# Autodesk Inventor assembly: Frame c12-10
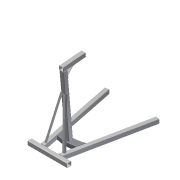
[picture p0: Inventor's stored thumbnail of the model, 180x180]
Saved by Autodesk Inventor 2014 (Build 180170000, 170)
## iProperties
Created: 2011-01
Part Number: Frame c12-10
Document SubType Name: Assembly
Designer: Thom Tremblay
_FrameDoc: Frame Assembly
_Version: 15.0.0
Author: Thom Tremblay
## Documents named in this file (20)
- C:\Inventor 2014 Essentials\Assemblies\Chapter 12\Frame\Frame c12-10.iam
- C:\Inventor 2014 Essentials\Assemblies\Chapter 12\Frame\Skeleton-c12-10.ipt
- C:\Inventor 2014 Essentials\Assemblies\Chapter 12\Frame\ANSI L 1.5 x 1.5 x 3_16 00000005.ipt
- ANSI L 1.5 x 1.5 x 3_16 00000005.ipt
- C:\Inventor 2014 Essentials\Assemblies\Chapter 12\Frame\ANSI L 1.5 x 1.5 x 3_16 00000006.ipt
- ANSI L 1.5 x 1.5 x 3_16 00000006.ipt
- C:\Inventor 2014 Essentials\Assemblies\Chapter 12\Frame\ANSI 2 1_4x5_16 00000007.ipt
- ANSI 2 1_4x5_16 00000007.ipt
- C:\Inventor 2014 Essentials\Assemblies\Chapter 12\Frame\ANSI 3x3x3_16 00000049.ipt
- ANSI 3x3x3_16 00000049.ipt
- C:\Inventor 2014 Essentials\Assemblies\Chapter 12\Frame\ANSI 3x3x3_16 00000050.ipt
- ANSI 3x3x3_16 00000050.ipt
- C:\Inventor 2014 Essentials\Assemblies\Chapter 12\Frame\ANSI 3x3x3_16 00000051.ipt
- ANSI 3x3x3_16 00000051.ipt
- C:\Inventor 2014 Essentials\Assemblies\Chapter 12\Frame\ANSI 3x3x3_16 00000052.ipt
- ANSI 3x3x3_16 00000052.ipt
- C:\Inventor 2014 Essentials\Assemblies\Chapter 12\Frame\ANSI 3x3x3_16 00000054.ipt
- ANSI 3x3x3_16 00000054.ipt
- C:\Inventor 2014 Essentials\Assemblies\Chapter 12\Frame\ANSI 5x3x3_16 00000058.ipt
- ANSI 5x3x3_16 00000058.ipt
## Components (10 placed, 10 different names)
1. Frame Reference Model
2. ANSI L 1.5 x 1.5 x 3_16 00000005:1
3. ANSI L 1.5 x 1.5 x 3_16 00000006:1
4. ANSI 2 1_4x5_16 00000007:1
5. ANSI 3x3x3_16 00000049:1
6. ANSI 3x3x3_16 00000050:1
7. ANSI 3x3x3_16 00000051:1
8. ANSI 3x3x3_16 00000052:1
9. ANSI 3x3x3_16 00000054:1
10. ANSI 5x3x3_16 00000058:1
